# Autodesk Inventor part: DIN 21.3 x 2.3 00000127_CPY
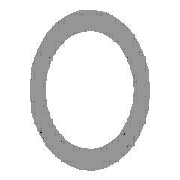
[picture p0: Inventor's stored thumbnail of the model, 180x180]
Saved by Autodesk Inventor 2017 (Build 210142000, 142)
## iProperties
Created: 2017-11
Part Number: DIN 21.3 x 2.3 00000127_CPY
Material: Steel, Mild
Description: Pipe
Document SubType Name: Modeling
Standard: DIN
Designer: iusti
Standard Revision: 2006-07
Standards Organization: DIN
Language: en-US
Size Designation: 21.3 x 2.3
Categories: <MemberInstance><Categories><Category DisplayName="Structural Shapes" InternalName="089c4875-fa83-4c05-b084-43b9cc11f5ed" Mnemonic="GRDR"><CategoryParameter Dis
Stock Number: 21.3 x 2.3
Density: 7.85 g/cm^3
Appearance: Semi-Polished
_CCFamilyMember: 1
_CCFamilyDisplayName: DIN EN 10210-2 - Pipe
_FrameMemberDoc: Frame Member File
_Version: 15.0.0
_GetPNFromCC: 1
IsCustomPart: 1
Author: iusti
G_L: 500.000 mm
G_W: 21.300 mm
G_H: 21.300 mm
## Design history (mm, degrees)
node "Start plane"
node "End plane"
sketch "Sketch"
  geometry: C1 r 8.35 at (0, 0); C2 r 10.65 at (0, 0); 2 further points
  constraints: 3 coincident, 2 centre point
  dimensions: "d0" = 21.3 diameter of C2 (= G_H); "d1" = 2.3 radial gap between concentric circles of C2 C1 (= G_T)
extrude "Body" new body sketch "Sketch" stored distance "d2" = 500 (= G_L); taper "d3" = 0 deg
node "Driven Length"
  sketch "Sketch3"
    geometry: L1 (0, 0)-(10, 0) reference
    constraints: 2 end point, 1 horizontal
  workplane "Work Plane3"
  sketch "Sketch4"
    geometry: L1 (-2, 0)-(12, 0) reference; L2 (-2, 500)-(12, 500) reference
    dimensions: "d7" = 500 distance between parallel lines of L1 L2 (derived)
body "Solid1"
other parameters: "G_H" = 21.3 [user parameter; used in 1 equation term], "G_T" = 2.3 [user parameter; used in 1 equation term], "G_L" = 500 (= d7) [user parameter; used in 1 equation term], "G_OFFSET_START" = 0 [user parameter; used in 1 equation term], "G_OFFSET_END" = 0 [user parameter; used in 1 equation term], "d4" = 0 (computed from G_OFFSET_START), "d6" = 90 deg
